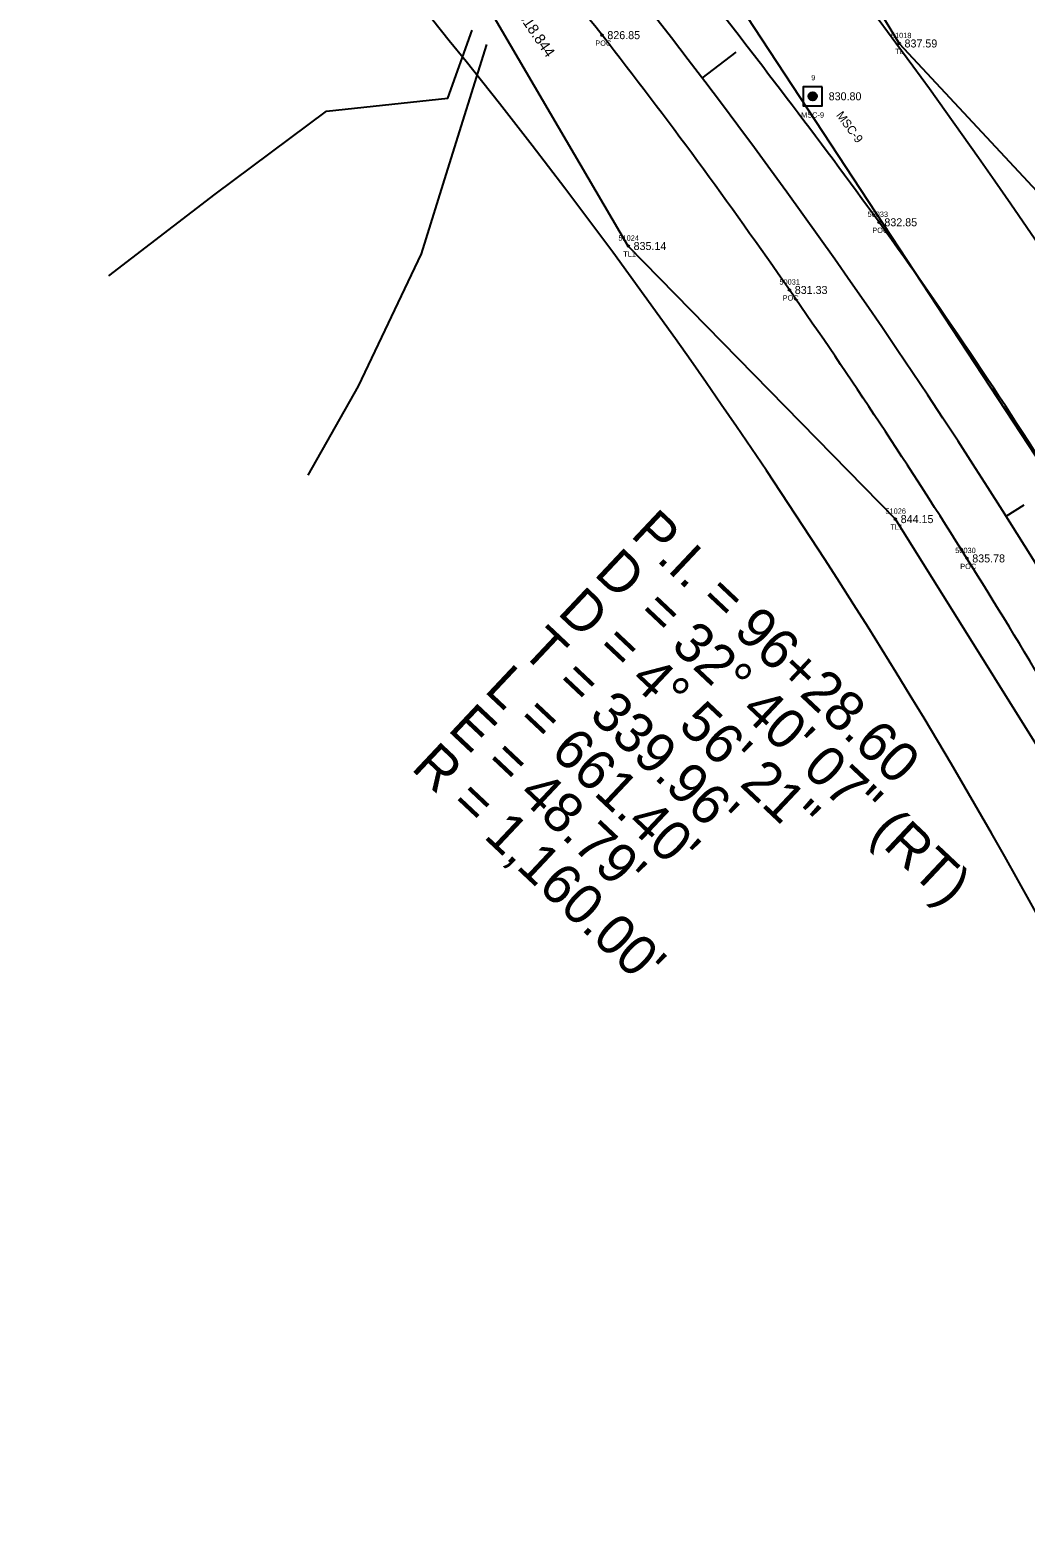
# Model space of a CAD drawing. Extents: x 1378245 to 1381654, y 996521 to 1000567.
# Drawn here: x 1380233.5 to 1380420.1, y 998046 to 998327.2 of the extents above; entities that cross this region are included whole.
import ezdxf

# ---------------------------------------------------------------- set-up
doc = ezdxf.new("R2010")
doc.units = 0
for name, color, linetype in [('RD_EX_H2O', 7, 'Continuous'), ('RD_EX_Road', 7, 'Continuous'), ('RD_EX_Road_txCode', 7, 'Continuous'), ('RD_EX_RW', 7, 'Continuous'), ('RD_EX_SU_Elec', 7, 'Continuous'), ('RD_EX_TX_Road_ELEV', 7, 'Continuous'), ('RD_EX_TX_VEG_ELEV', 7, 'Continuous'), ('RD_EX_VEG', 7, 'Continuous'), ('RD_EX_VEG_txCode', 7, 'Continuous'), ('RD_HC_Cl', 7, 'Continuous'), ('RD_HC_Data', 7, 'Continuous'), ('RD_HC_Data_Tic', 7, 'Continuous'), ('RD_HC_Survey', 7, 'Continuous'), ('RD_HC_Survey_ELEV', 7, 'Continuous'), ('RD_HC_Survey_txCode', 7, 'Continuous'), ('RD_SMD_Locator', 7, 'Continuous'), ('RD_TX_Misc1', 7, 'Continuous'), ('RD_TX_Pipe_ElevEX', 7, 'Continuous')]:
    doc.layers.add(name, color=color, linetype=linetype)

msp = doc.modelspace()

# ---------------------------------------------------------------- linework, layer by layer
at = {"layer": 'RD_EX_H2O'}
for points in [[(1380248.26, 998281.07), (1380268.23, 998296.41), (1380289.12, 998311.97), (1380311.81, 998314.4), (1380316.43, 998327.16)], [(1380285.64, 998243.75), (1380295.09, 998260.41), (1380306.92, 998285.24), (1380311.84, 998301.11), (1380319.15, 998324.46)]]:
    msp.add_lwpolyline(points, dxfattribs=at)
at = {"layer": 'RD_EX_Road'}
for points in [[(1380571.28, 997900.85), (1380553.84, 997963.23), (1380535.07, 998018.79), (1380510.81, 998079.18), (1380486.36, 998133.16), (1380458.39, 998185.94), (1380428.11, 998238.22), (1380392.69, 998291.14), (1380357.52, 998337.62), (1380319.37, 998385.16), (1380279.26, 998428.68), (1380239.6, 998468.13), (1380183.37, 998518.83)], [(1380551.89, 997897.33), (1380534.24, 997958.2), (1380514.83, 998013.47), (1380491.08, 998070.75), (1380467.52, 998124.4), (1380439.88, 998176.53), (1380409.17, 998228.12), (1380375.89, 998278.45), (1380340.75, 998326.22), (1380303.33, 998371.14), (1380263.98, 998413.97), (1380224.66, 998452.64), (1380168.71, 998504.79)]]:
    msp.add_spline(points, degree=3, dxfattribs=at)
at = {"layer": 'RD_EX_RW'}
for radius in [1193, 1127]:
    msp.add_arc((1379435.86, 997616.44), radius, 14.99564, 47.66422, dxfattribs=at)
at = {"layer": 'RD_EX_SU_Elec'}
msp.add_lwpolyline([(1378514.25, 999944.12), (1378777.7, 999831.22), (1379190.17, 999461.05), (1379403.33, 999174.04), (1379756.94, 998924.25), (1380051.16, 998659.97), (1380327.91, 998390.65), (1380546.23, 998058.37)], dxfattribs=at)
at = {"layer": 'RD_EX_VEG'}
for points in [[(1380572.26, 997755.47), (1380563.06, 997802.88), (1380548.57, 997859.96), (1380528.6, 997926.15), (1380512.76, 997988.52), (1380488.02, 998054.97), (1380458.55, 998120.18), (1380432.73, 998176.36), (1380395.75, 998235.49), (1380345.67, 998286.69), (1380306.05, 998354.38), (1380256.57, 998407.41), (1380203.97, 998456.66), (1380158.7, 998500.55), (1380112.46, 998542.96), (1380070.42, 998580.38), (1380028.44, 998619.77), (1379982.76, 998660.07), (1379934.04, 998703.39), (1379891.18, 998743.94), (1379841.91, 998788.98), (1379798.41, 998828.62), (1379752.34, 998871.98), (1379716.47, 998899.23)], [(1380236.78, 998513.81), (1380245.91, 998495.33), (1380309.18, 998454.94), (1380350.89, 998399.56), (1380396.47, 998324.66), (1380448.94, 998268.37), (1380485.63, 998232.92), (1380499.56, 998226.61)]]:
    msp.add_lwpolyline(points, dxfattribs=at)
at = {"layer": 'RD_HC_Cl'}
msp.add_arc((1379435.86, 997616.44), 1160, 14.99564, 47.66422, dxfattribs=at)
at = {"layer": 'RD_HC_Data_Tic'}
for p, q in [((1380359.53, 998318.17), (1380365.9, 998323.01)), ((1380416.52, 998236.03), (1380419.9, 998238.17))]:
    msp.add_line(p, q, dxfattribs=at)
at = {"layer": 'RD_HC_Survey'}
for p, q in [((1380379.5, 998314.58), (1380379.5, 998314.94)), ((1380379.52, 998314.49), (1380379.52, 998315.02)), ((1380379.55, 998314.43), (1380379.55, 998315.08)), ((1380379.57, 998314.38), (1380379.57, 998315.13)), ((1380379.6, 998314.34), (1380379.6, 998315.18)), ((1380379.62, 998314.31), (1380379.62, 998315.21)), ((1380379.65, 998314.27), (1380379.65, 998315.25)), ((1380379.67, 998314.24), (1380379.67, 998315.28)), ((1380379.7, 998314.22), (1380379.7, 998315.3)), ((1380379.72, 998314.19), (1380379.72, 998315.33)), ((1380379.75, 998314.17), (1380379.75, 998315.35)), ((1380379.77, 998314.15), (1380379.77, 998315.37)), ((1380379.8, 998314.13), (1380379.8, 998315.39)), ((1380379.82, 998314.11), (1380379.82, 998315.41)), ((1380379.85, 998314.1), (1380379.85, 998315.42)), ((1380379.87, 998314.08), (1380379.87, 998315.44)), ((1380379.9, 998314.07), (1380379.9, 998315.45)), ((1380379.92, 998314.06), (1380379.92, 998315.46)), ((1380379.95, 998314.04), (1380379.95, 998315.47)), ((1380379.97, 998314.03), (1380379.97, 998315.48)), ((1380380, 998314.03), (1380380, 998315.49)), ((1380380.02, 998314.02), (1380380.02, 998315.5)), ((1380380.05, 998314.01), (1380380.05, 998315.51)), ((1380380.07, 998314), (1380380.07, 998315.51)), ((1380380.1, 998314), (1380380.1, 998315.52)), ((1380380.12, 998313.99), (1380380.12, 998315.53)), ((1380380.15, 998313.99), (1380380.15, 998315.53)), ((1380380.17, 998313.99), (1380380.17, 998315.53)), ((1380380.2, 998313.98), (1380380.2, 998315.53)), ((1380380.22, 998313.98), (1380380.22, 998315.54)), ((1380380.25, 998313.98), (1380380.25, 998315.54)), ((1380380.27, 998313.98), (1380380.27, 998315.54)), ((1380380.3, 998313.98), (1380380.3, 998315.54)), ((1380380.32, 998313.98), (1380380.32, 998315.53)), ((1380380.35, 998313.99), (1380380.35, 998315.53)), ((1380380.37, 998313.99), (1380380.37, 998315.53)), ((1380380.4, 998314), (1380380.4, 998315.52)), ((1380380.42, 998314), (1380380.42, 998315.52)), ((1380380.45, 998314.01), (1380380.45, 998315.51)), ((1380380.47, 998314.01), (1380380.47, 998315.5)), ((1380380.5, 998314.02), (1380380.5, 998315.5)), ((1380380.52, 998314.03), (1380380.52, 998315.49)), ((1380380.55, 998314.04), (1380380.55, 998315.48)), ((1380380.57, 998314.05), (1380380.57, 998315.47)), ((1380380.6, 998314.06), (1380380.6, 998315.46)), ((1380380.62, 998314.07), (1380380.62, 998315.44)), ((1380380.65, 998314.09), (1380380.65, 998315.43)), ((1380380.67, 998314.1), (1380380.67, 998315.41)), ((1380380.7, 998314.12), (1380380.7, 998315.4)), ((1380380.72, 998314.14), (1380380.72, 998315.38)), ((1380380.75, 998314.16), (1380380.75, 998315.36)), ((1380380.77, 998314.18), (1380380.77, 998315.34)), ((1380380.8, 998314.2), (1380380.8, 998315.31)), ((1380380.82, 998314.23), (1380380.82, 998315.29)), ((1380380.85, 998314.26), (1380380.85, 998315.26)), ((1380380.87, 998314.29), (1380380.87, 998315.23)), ((1380380.9, 998314.32), (1380380.9, 998315.19)), ((1380380.92, 998314.36), (1380380.92, 998315.15)), ((1380380.95, 998314.41), (1380380.95, 998315.11)), ((1380380.97, 998314.46), (1380380.97, 998315.05)), ((1380381, 998314.53), (1380381, 998314.98)), ((1380381.02, 998314.65), (1380381.02, 998314.87))]:
    msp.add_line(p, q, dxfattribs=at)
msp.add_lwpolyline([(1380382.02, 998316.53), (1380378.48, 998316.53), (1380378.48, 998312.99), (1380382.02, 998312.99)], close=True, dxfattribs=at)
msp.add_circle((1380380.25, 998314.76), 0.777, dxfattribs=at)
at = {"layer": 'RD_SMD_Locator'}
for centre, radius in [((1380340.75, 998326.22), 0.15), ((1380396.47, 998324.66), 0.15), ((1380380.25, 998314.76), 0.075), ((1380392.69, 998291.14), 0.15), ((1380345.67, 998286.69), 0.15), ((1380375.89, 998278.45), 0.15), ((1380395.75, 998235.49), 0.15), ((1380409.17, 998228.12), 0.15)]:
    msp.add_circle(centre, radius, dxfattribs=at)

# ---------------------------------------------------------------- texts
at = {"layer": 'RD_EX_Road_txCode'}
for s, p in [('POC', (1380339.48, 998324.22)), ('50033', (1380390.53, 998292.14)), ('POC', (1380391.42, 998289.14)), ('50031', (1380374.01, 998279.45)), ('POC', (1380374.62, 998276.45)), ('50030', (1380406.98, 998229.12)), ('POC', (1380407.91, 998226.12))]:
    msp.add_text(s, height=1, dxfattribs=at).set_placement(p)
at = {"layer": 'RD_EX_TX_Road_ELEV'}
for s, p in [('826.85', (1380341.75, 998325.47)), ('832.85', (1380393.69, 998290.39)), ('831.33', (1380376.89, 998277.7)), ('835.78', (1380410.17, 998227.37))]:
    msp.add_text(s, height=1.5, dxfattribs=at).set_placement(p)
at = {"layer": 'RD_EX_TX_VEG_ELEV'}
for s, p in [('837.59', (1380397.47, 998323.91)), ('835.14', (1380346.67, 998285.94)), ('844.15', (1380396.75, 998234.74))]:
    msp.add_text(s, height=1.5, dxfattribs=at).set_placement(p)
at = {"layer": 'RD_EX_VEG_txCode'}
for s, p in [('51018', (1380394.92, 998325.66)), ('TL', (1380395.7, 998322.66)), ('51024', (1380343.83, 998287.69)), ('TL1', (1380344.73, 998284.69)), ('51026', (1380393.89, 998236.49)), ('TL1', (1380394.81, 998233.49))]:
    msp.add_text(s, height=1, dxfattribs=at).set_placement(p)
at = {"layer": 'RD_HC_Data'}
for s, p in [('P.I. = 96+28.60', (1380345.9, 998232.37)), ('D', (1380339.04, 998225.08)), ('D = 4%%d 56\' 21"', (1380332.19, 998217.8)), ('    = 32%%d 40\' 07" (RT)', (1380339.04, 998225.08)), ("T = 339.96'", (1380325.33, 998210.52)), ("L = 661.40'", (1380318.48, 998203.24)), ("E = 48.79'", (1380311.63, 998195.96)), ("R = 1,160.00'", (1380304.77, 998188.67))]:
    msp.add_text(s, height=7.5, rotation=316.736, dxfattribs=at).set_placement(p)
at = {"layer": 'RD_HC_Survey_ELEV'}
msp.add_text('830.80', height=1.5, dxfattribs=at).set_placement((1380383.25, 998314.01))
msp.add_text('830.80', height=1.5, dxfattribs=at).set_placement((1380383.25, 998314.01))
at = {"layer": 'RD_HC_Survey_txCode'}
for s, p in [('9', (1380379.97, 998317.76)), ('9', (1380379.97, 998317.76)), ('MSC-9', (1380378.08, 998310.76)), ('MSC-9', (1380378.08, 998310.76))]:
    msp.add_text(s, height=1, dxfattribs=at).set_placement(p)
at = {"layer": 'RD_TX_Misc1'}
msp.add_text('MSC-9', height=1.6, rotation=306.4593, dxfattribs=at).set_placement((1380384.57, 998311.19))
at = {"layer": 'RD_TX_Pipe_ElevEX'}
msp.add_text('EL=818.844', height=2, rotation=304.3177, dxfattribs=at).set_placement((1380322.23, 998333.85))

doc.saveas('drawing.dxf')
